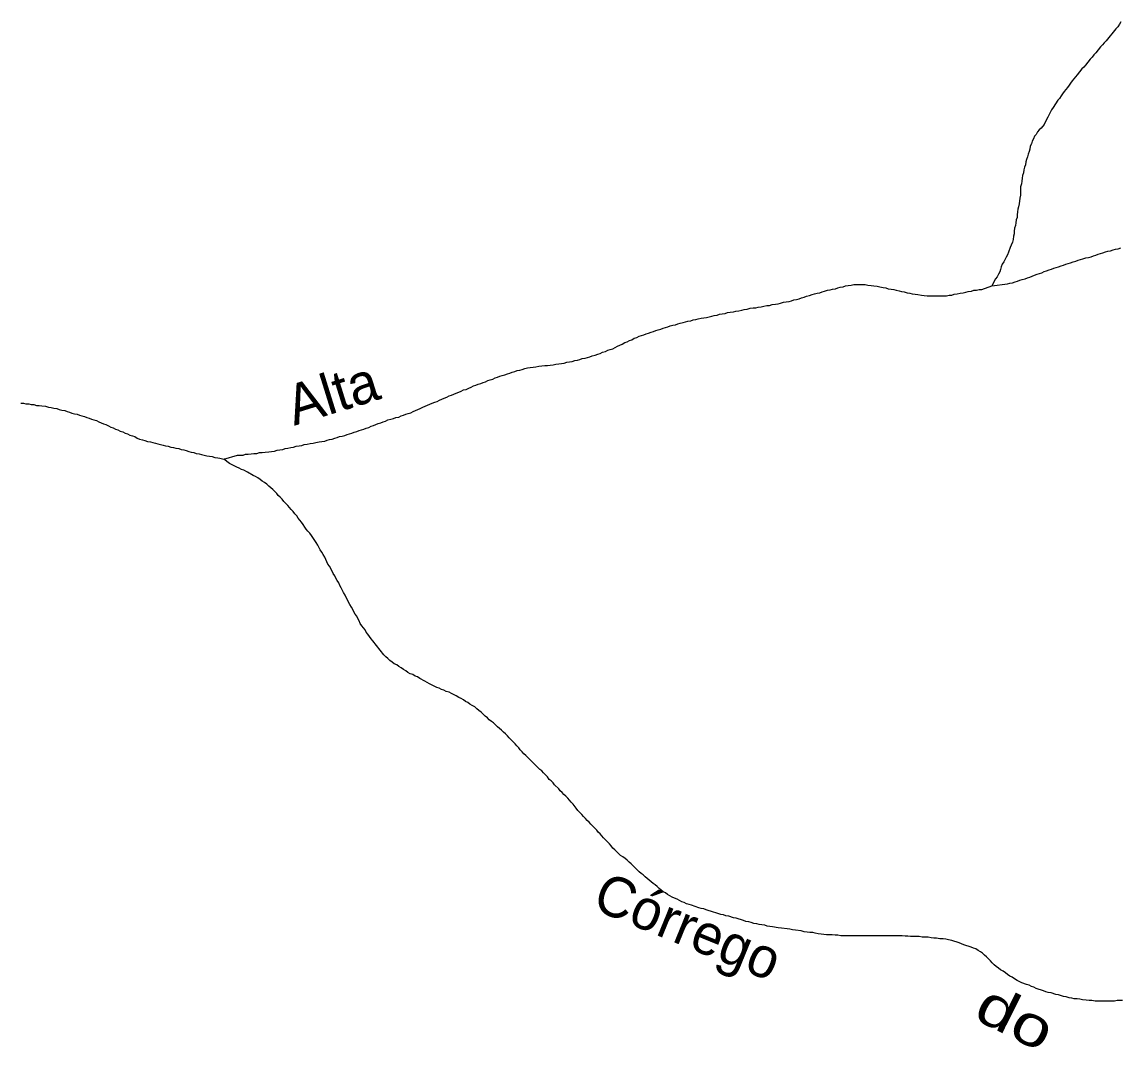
# Model space of a CAD drawing. Extents: x 652.3 to 678, y 7316.9 to 7344.9.
# Drawn here: x 668.434 to 670.618, y 7334.156 to 7336.197 of the extents above; entities that cross this region are included whole.
import ezdxf
from ezdxf.enums import TextEntityAlignment as Align

# ---------------------------------------------------------------- set-up
doc = ezdxf.new("R2010")
doc.units = 0
doc.header["$LTSCALE"] = 0.032
doc.layers.add('61', color=7, linetype='Continuous')
doc.layers.add('7', color=7, linetype='Continuous', lineweight=25)

msp = doc.modelspace()

# ---------------------------------------------------------------- linework, layer by layer
at = {"layer": '7'}
msp.add_line((668.8274, 7335.3292), (668.8353, 7335.3276), dxfattribs=at)
for points in [[(670.62, 7336.1973), (670.6169, 7336.1926), (670.6137, 7336.1878), (670.6097, 7336.1838), (670.5906, 7336.1599), (670.5866, 7336.1559), (670.5834, 7336.152), (670.5795, 7336.148), (670.5699, 7336.1361), (670.5659, 7336.1321), (670.5627, 7336.1273), (670.5588, 7336.1233), (670.5492, 7336.1114), (670.546, 7336.1074), (670.5421, 7336.1042), (670.5325, 7336.0923), (670.5293, 7336.0883), (670.523, 7336.0804), (670.5198, 7336.0756), (670.5166, 7336.0716), (670.5134, 7336.0668), (670.5102, 7336.0629), (670.507, 7336.0589), (670.5039, 7336.0541), (670.5007, 7336.0501), (670.4975, 7336.0453), (670.4943, 7336.0414), (670.4848, 7336.027), (670.4816, 7336.0223), (670.4744, 7336.008), (670.472, 7336.0032), (670.4673, 7335.9936), (670.4609, 7335.9857), (670.4569, 7335.9825), (670.4537, 7335.9785), (670.4514, 7335.9737), (670.4482, 7335.9698), (670.4458, 7335.965), (670.4434, 7335.9602), (670.4418, 7335.9546), (670.4394, 7335.9499), (670.4386, 7335.9443), (670.437, 7335.9395), (670.4354, 7335.934), (670.4338, 7335.9292), (670.4323, 7335.9236), (670.4307, 7335.9188), (670.4299, 7335.9133), (670.4283, 7335.9085), (670.4267, 7335.9029), (670.4259, 7335.8974), (670.4243, 7335.8918), (670.4235, 7335.8862), (670.4227, 7335.8806), (670.4219, 7335.8751), (670.4203, 7335.8695), (670.4203, 7335.8528), (670.4187, 7335.8464), (670.4171, 7335.8353), (670.4163, 7335.8297), (670.4147, 7335.8249), (670.414, 7335.8194), (670.4132, 7335.8138), (670.4132, 7335.8082), (670.4116, 7335.8035), (670.4108, 7335.7979), (670.41, 7335.7923), (670.4084, 7335.7868), (670.4076, 7335.7812), (670.4076, 7335.7756), (670.406, 7335.7708), (670.4052, 7335.7645), (670.4044, 7335.7589), (670.4012, 7335.7533), (670.3996, 7335.7486), (670.3964, 7335.739), (670.3941, 7335.7342), (670.3917, 7335.7295), (670.3869, 7335.7199), (670.3837, 7335.7151), (670.3813, 7335.7104), (670.3805, 7335.7048), (670.3789, 7335.7), (670.3766, 7335.6952), (670.3734, 7335.6905), (670.3702, 7335.6865), (670.363, 7335.6722)], [(670.363, 7335.6722), (670.3941, 7335.6761), (670.3988, 7335.6777), (670.4044, 7335.6785), (670.4092, 7335.6801), (670.414, 7335.6817), (670.4187, 7335.6833), (670.4235, 7335.6849), (670.4291, 7335.6865), (670.4338, 7335.6881), (670.4386, 7335.6897), (670.4434, 7335.6913), (670.4482, 7335.6937), (670.4529, 7335.6952), (670.4577, 7335.6968), (670.4625, 7335.6984), (670.4673, 7335.7008), (670.472, 7335.7024), (670.4768, 7335.704), (670.4816, 7335.7056), (670.4864, 7335.7072), (670.4911, 7335.7088), (670.4959, 7335.7104), (670.5007, 7335.712), (670.5055, 7335.7135), (670.5102, 7335.7151), (670.515, 7335.7167), (670.5198, 7335.7183), (670.5246, 7335.7199), (670.5301, 7335.7215), (670.5349, 7335.7231), (670.5397, 7335.7247), (670.5444, 7335.7263), (670.55, 7335.7279), (670.5556, 7335.7287), (670.5604, 7335.7303), (670.5651, 7335.7318), (670.5699, 7335.7334), (670.5747, 7335.735), (670.5795, 7335.7366), (670.5842, 7335.7382), (670.589, 7335.7398), (670.5938, 7335.7414), (670.5993, 7335.7422), (670.6041, 7335.7438), (670.6089, 7335.7454), (670.6145, 7335.7462), (670.62, 7335.7478)], [(669.6374, 7335.5608), (669.6421, 7335.5632), (669.6469, 7335.5648), (669.6517, 7335.5679), (669.6565, 7335.5695), (669.6612, 7335.5719), (669.666, 7335.5735), (669.6708, 7335.5751), (669.6756, 7335.5767), (669.6803, 7335.5783), (669.6851, 7335.5799), (669.6899, 7335.5815), (669.6947, 7335.5831), (669.6994, 7335.5846), (669.7042, 7335.5862), (669.709, 7335.5878), (669.7137, 7335.5894), (669.7185, 7335.591), (669.7233, 7335.5926), (669.7281, 7335.5942), (669.7336, 7335.595), (669.7384, 7335.5966), (669.7432, 7335.5982), (669.7488, 7335.599), (669.7535, 7335.6006), (669.7583, 7335.6022), (669.7639, 7335.6029), (669.7687, 7335.6045), (669.7742, 7335.6053), (669.779, 7335.6069), (669.7846, 7335.6077), (669.7901, 7335.6085), (669.7957, 7335.6093), (669.8005, 7335.6109), (669.806, 7335.6117), (669.8108, 7335.6133), (669.8164, 7335.6141), (669.8212, 7335.6157), (669.8267, 7335.6165), (669.8323, 7335.6173), (669.8371, 7335.6189), (669.8426, 7335.6197), (669.849, 7335.6205), (669.8538, 7335.622), (669.8594, 7335.6228), (669.8657, 7335.6236), (669.8705, 7335.6252), (669.8761, 7335.626), (669.8824, 7335.6276), (669.888, 7335.6284), (669.8936, 7335.6284), (669.8983, 7335.63), (669.9039, 7335.6308), (669.9095, 7335.6316), (669.9151, 7335.6332), (669.9206, 7335.6332), (669.9262, 7335.6348), (669.9326, 7335.6356), (669.9381, 7335.6364), (669.9429, 7335.638), (669.9485, 7335.6395), (669.954, 7335.6403), (669.9596, 7335.6411), (669.9644, 7335.6427), (669.9692, 7335.6443), (669.9747, 7335.6451), (669.9795, 7335.6467), (669.9843, 7335.6483), (669.9899, 7335.6499), (669.9946, 7335.6515), (670.0002, 7335.6531), (670.0058, 7335.6547), (670.0105, 7335.6563), (670.0153, 7335.6578), (670.0209, 7335.6586), (670.0257, 7335.6602), (670.0304, 7335.6618), (670.036, 7335.6634), (670.0416, 7335.6642), (670.0463, 7335.6658), (670.0519, 7335.6666), (670.0567, 7335.6682), (670.0615, 7335.6698), (670.067, 7335.6706), (670.0718, 7335.6722), (670.0774, 7335.673), (670.0829, 7335.6738), (670.0885, 7335.6746), (670.0941, 7335.6746), (670.0997, 7335.6746), (670.1052, 7335.6746), (670.1108, 7335.6746), (670.1164, 7335.6738), (670.1227, 7335.673), (670.1283, 7335.6722), (670.1347, 7335.6714), (670.1402, 7335.6706), (670.1466, 7335.669), (670.1522, 7335.6682), (670.1569, 7335.6666), (670.1625, 7335.6658)], [(670.1625, 7335.6658), (670.1681, 7335.665), (670.1729, 7335.6634), (670.1784, 7335.6626), (670.1832, 7335.661), (670.1888, 7335.6602), (670.1943, 7335.6586), (670.1999, 7335.6578), (670.2047, 7335.6563), (670.2103, 7335.6555), (670.2158, 7335.6547), (670.223, 7335.6539), (670.2286, 7335.6531), (670.2341, 7335.6523), (670.2397, 7335.6523), (670.2453, 7335.6523), (670.2508, 7335.6523), (670.2564, 7335.6523), (670.262, 7335.6523), (670.2675, 7335.6523), (670.2731, 7335.6523), (670.2779, 7335.6539), (670.2835, 7335.6539), (670.2882, 7335.6555), (670.2938, 7335.6563), (670.3002, 7335.6578), (670.3057, 7335.6586), (670.3113, 7335.6594), (670.3161, 7335.661), (670.3224, 7335.6618), (670.3272, 7335.6634), (670.3328, 7335.6634), (670.3376, 7335.665), (670.3429, 7335.665)], [(670.3429, 7335.665), (670.363, 7335.6722), (670.363, 7335.6722)], [(669.1377, 7335.3961), (669.1424, 7335.3985), (669.1472, 7335.4), (669.152, 7335.4016), (669.1568, 7335.4032), (669.1615, 7335.4056), (669.1671, 7335.4072), (669.1727, 7335.408), (669.1775, 7335.4104), (669.183, 7335.4112), (669.1878, 7335.4136), (669.1926, 7335.4152), (669.1973, 7335.4168), (669.2021, 7335.4183), (669.2069, 7335.4199), (669.2117, 7335.4223), (669.2164, 7335.4239), (669.2212, 7335.4263), (669.226, 7335.4279), (669.2308, 7335.4311), (669.2355, 7335.4327), (669.2403, 7335.4351), (669.2451, 7335.4366), (669.2499, 7335.439), (669.2546, 7335.4406), (669.2594, 7335.4422), (669.2642, 7335.4446), (669.269, 7335.447), (669.2737, 7335.4486), (669.2785, 7335.451), (669.2833, 7335.4534), (669.2881, 7335.4549), (669.2928, 7335.4565), (669.2976, 7335.4589), (669.3024, 7335.4605), (669.3072, 7335.4629), (669.3119, 7335.4653), (669.3175, 7335.4661), (669.3223, 7335.4685), (669.327, 7335.4709), (669.3318, 7335.4732), (669.3366, 7335.4748), (669.3414, 7335.4764), (669.3461, 7335.478), (669.3509, 7335.4796), (669.3557, 7335.4812), (669.3605, 7335.4836), (669.3652, 7335.4852), (669.37, 7335.4868), (669.3748, 7335.4892), (669.3796, 7335.4908), (669.3843, 7335.4923), (669.3891, 7335.4939), (669.3939, 7335.4955), (669.3995, 7335.4971), (669.4042, 7335.4987), (669.409, 7335.5003), (669.4138, 7335.5019), (669.4185, 7335.5035), (669.4241, 7335.5043), (669.4289, 7335.5059), (669.4337, 7335.5075), (669.4392, 7335.5091), (669.4448, 7335.5099), (669.4504, 7335.5106), (669.4559, 7335.5114), (669.4615, 7335.5122), (669.4679, 7335.513), (669.4735, 7335.5138), (669.479, 7335.5138), (669.4846, 7335.5146), (669.4902, 7335.5154), (669.4957, 7335.5162), (669.5013, 7335.517), (669.5069, 7335.5178), (669.5124, 7335.5186), (669.5172, 7335.5202), (669.5228, 7335.521), (669.5284, 7335.5218), (669.5331, 7335.5234), (669.5387, 7335.5242), (669.5435, 7335.5258), (669.5482, 7335.5274), (669.5538, 7335.5282), (669.5586, 7335.5297), (669.5634, 7335.5313), (669.5681, 7335.5329), (669.5737, 7335.5345), (669.5793, 7335.5361), (669.5841, 7335.5377), (669.5888, 7335.5401), (669.5944, 7335.5417), (669.5992, 7335.5441), (669.6039, 7335.5457), (669.6087, 7335.5472), (669.6135, 7335.5496), (669.6183, 7335.552), (669.623, 7335.5544), (669.6278, 7335.556), (669.6326, 7335.5592), (669.6374, 7335.5608)], [(668.4311, 7335.439), (668.4367, 7335.439), (668.4414, 7335.4374), (668.447, 7335.4374), (668.4518, 7335.4359), (668.4574, 7335.4359), (668.4621, 7335.4343), (668.4677, 7335.4343), (668.4733, 7335.4335), (668.4804, 7335.4327), (668.486, 7335.4311), (668.4916, 7335.4303), (668.4971, 7335.4287), (668.5027, 7335.4279), (668.5075, 7335.4263), (668.5131, 7335.4247), (668.5186, 7335.4239), (668.5234, 7335.4223), (668.5282, 7335.4207), (668.5329, 7335.4191), (668.5377, 7335.4176), (668.5433, 7335.4168), (668.5481, 7335.4152), (668.5528, 7335.4136), (668.5576, 7335.412), (668.5624, 7335.4104), (668.5672, 7335.4088), (668.5719, 7335.4072), (668.5767, 7335.4056), (668.5815, 7335.404), (668.5863, 7335.4016), (668.591, 7335.4)], [(668.591, 7335.4), (668.5958, 7335.3977), (668.6006, 7335.3961), (668.6054, 7335.3937), (668.6101, 7335.3913), (668.6149, 7335.3897), (668.6197, 7335.3873), (668.6245, 7335.3857), (668.6292, 7335.3833), (668.634, 7335.3817), (668.6388, 7335.3794), (668.6435, 7335.3778), (668.6483, 7335.3754), (668.6531, 7335.3738), (668.6579, 7335.3722), (668.6626, 7335.369), (668.6674, 7335.3674), (668.673, 7335.3658), (668.6778, 7335.3642), (668.6833, 7335.3626), (668.6889, 7335.3619), (668.6937, 7335.3603), (668.6992, 7335.3595), (668.704, 7335.3579), (668.7088, 7335.3563), (668.7144, 7335.3555), (668.7191, 7335.3539), (668.7247, 7335.3531), (668.7295, 7335.3515), (668.7351, 7335.3507), (668.7398, 7335.3491), (668.7454, 7335.3483), (668.7502, 7335.3467), (668.7557, 7335.3459), (668.7605, 7335.3443), (668.7653, 7335.3428), (668.7701, 7335.3412), (668.7756, 7335.3404), (668.7804, 7335.3388), (668.786, 7335.338), (668.7907, 7335.3364), (668.7963, 7335.3356), (668.8011, 7335.334), (668.8067, 7335.3332), (668.8122, 7335.3324), (668.817, 7335.3308), (668.8234, 7335.33), (668.8274, 7335.3292)], [(668.8353, 7335.3276), (668.8624, 7335.3356), (668.8679, 7335.3356), (668.8735, 7335.3356), (668.8783, 7335.3372), (668.8838, 7335.3372), (668.8894, 7335.338), (668.895, 7335.3388), (668.9006, 7335.3388), (668.9061, 7335.3404), (668.9117, 7335.3404), (668.9173, 7335.3412), (668.9244, 7335.342), (668.93, 7335.3428), (668.9356, 7335.3436), (668.9411, 7335.3451), (668.9467, 7335.3459), (668.9523, 7335.3467), (668.957, 7335.3483), (668.9626, 7335.3491), (668.9682, 7335.3507), (668.9738, 7335.3515), (668.9793, 7335.3531), (668.9849, 7335.3539), (668.9905, 7335.3547), (668.9952, 7335.3563), (669.0008, 7335.3571), (669.0072, 7335.3587), (669.0127, 7335.3595), (669.0183, 7335.3603), (669.0247, 7335.3619), (669.0303, 7335.3626), (669.0358, 7335.3634), (669.0406, 7335.365), (669.0454, 7335.3666), (669.0509, 7335.3674), (669.0557, 7335.369), (669.0605, 7335.3706), (669.0653, 7335.3722), (669.0708, 7335.373), (669.0756, 7335.3746), (669.0804, 7335.3762), (669.0852, 7335.3778), (669.0899, 7335.3794), (669.0947, 7335.3809), (669.0995, 7335.3825), (669.1043, 7335.3841), (669.109, 7335.3857), (669.1138, 7335.3873), (669.1186, 7335.3889), (669.1233, 7335.3905), (669.1281, 7335.3929), (669.1329, 7335.3945), (669.1377, 7335.3961)], [(668.9117, 7335.2839), (668.9077, 7335.2871), (668.9029, 7335.2902), (668.8982, 7335.2926), (668.8934, 7335.295), (668.8823, 7335.3014), (668.8751, 7335.3054), (668.8703, 7335.307), (668.8655, 7335.3093), (668.8608, 7335.3117), (668.8464, 7335.3189), (668.8353, 7335.3276)], [(669.3597, 7334.8128), (669.3549, 7334.816), (669.3469, 7334.824), (669.3422, 7334.8272), (669.3382, 7334.8303), (669.3342, 7334.8343), (669.3294, 7334.8375), (669.3247, 7334.8399), (669.3207, 7334.8431), (669.3159, 7334.8455), (669.3119, 7334.8486), (669.3072, 7334.851), (669.3024, 7334.8534), (669.2976, 7334.8566), (669.2881, 7334.8614), (669.2833, 7334.8638), (669.2777, 7334.8653), (669.2729, 7334.8677), (669.2682, 7334.8693), (669.2634, 7334.8717), (669.2586, 7334.8733), (669.2443, 7334.8805), (669.2395, 7334.8828), (669.2347, 7334.886), (669.2252, 7334.8908), (669.2204, 7334.894), (669.2156, 7334.8956), (669.2109, 7334.8988), (669.2061, 7334.9004), (669.2013, 7334.9027), (669.1973, 7334.9059), (669.1926, 7334.9091), (669.1878, 7334.9123), (669.183, 7334.9147), (669.179, 7334.9179), (669.1743, 7334.9202), (669.1703, 7334.9234), (669.1655, 7334.9266), (669.1615, 7334.9306), (669.1576, 7334.9338), (669.1536, 7334.9378), (669.1313, 7334.9656), (669.1281, 7334.9696), (669.1249, 7334.9744), (669.1218, 7334.9791), (669.1186, 7334.9831), (669.1162, 7334.9879), (669.1098, 7334.9958), (669.1066, 7335.0006), (669.1043, 7335.0054), (669.1019, 7335.0102), (669.0995, 7335.0149), (669.0963, 7335.0189), (669.0891, 7335.0332), (669.086, 7335.038), (669.0788, 7335.0523), (669.0764, 7335.0571), (669.0732, 7335.0619), (669.0684, 7335.0714), (669.0661, 7335.0762), (669.0637, 7335.081), (669.0605, 7335.0857), (669.0581, 7335.0905), (669.0557, 7335.0953), (669.0525, 7335.1001), (669.0478, 7335.1096), (669.0454, 7335.1144), (669.0422, 7335.1184), (669.0398, 7335.1231), (669.0382, 7335.1279), (669.0358, 7335.1327), (669.0326, 7335.1375), (669.0303, 7335.1422), (669.0271, 7335.147), (669.0223, 7335.1566), (669.0191, 7335.1613), (669.0096, 7335.1757), (669.0064, 7335.1804), (669.0024, 7335.1844), (668.9992, 7335.1884), (668.996, 7335.1924), (668.9929, 7335.1971), (668.9897, 7335.2019), (668.9833, 7335.2099), (668.9801, 7335.2147), (668.9761, 7335.2186), (668.973, 7335.2234), (668.969, 7335.2274), (668.9626, 7335.2353), (668.9586, 7335.2393), (668.9547, 7335.2433), (668.9515, 7335.2481), (668.9475, 7335.252), (668.9435, 7335.2552), (668.9403, 7335.2592), (668.9324, 7335.2672), (668.9284, 7335.2703), (668.9244, 7335.2735), (668.9204, 7335.2775), (668.9157, 7335.2807), (668.9117, 7335.2839)], [(669.8952, 7334.403), (669.8896, 7334.4038), (669.884, 7334.4054), (669.8793, 7334.407), (669.8737, 7334.4078), (669.8689, 7334.4094), (669.8546, 7334.4142), (669.849, 7334.415), (669.8395, 7334.4182), (669.8339, 7334.419), (669.8291, 7334.4206), (669.8236, 7334.4213), (669.814, 7334.4245), (669.8092, 7334.4261), (669.7949, 7334.4309), (669.7901, 7334.4325), (669.7846, 7334.4333), (669.7798, 7334.4349), (669.7655, 7334.4397), (669.7607, 7334.4412), (669.7559, 7334.4428), (669.7511, 7334.4452), (669.7464, 7334.4468), (669.7368, 7334.4516), (669.732, 7334.454), (669.7273, 7334.4556), (669.7225, 7334.4587), (669.7177, 7334.4611), (669.7137, 7334.4643), (669.709, 7334.4667), (669.705, 7334.4699), (669.701, 7334.4731), (669.697, 7334.477), (669.6931, 7334.4802), (669.6891, 7334.4834), (669.6851, 7334.4866), (669.6811, 7334.4898), (669.6771, 7334.493), (669.6732, 7334.4961), (669.6692, 7334.5001), (669.6652, 7334.5033), (669.6612, 7334.5065), (669.6453, 7334.5224), (669.6413, 7334.5256), (669.6374, 7334.5296), (669.6334, 7334.5327), (669.6286, 7334.5359), (669.6246, 7334.5391), (669.6207, 7334.5423), (669.6127, 7334.5503), (669.6087, 7334.5534), (669.6055, 7334.5582), (669.6024, 7334.5622), (669.5904, 7334.5741), (669.5841, 7334.5821), (669.5801, 7334.5853), (669.5769, 7334.5892), (669.565, 7334.6012), (669.5618, 7334.6052), (669.5578, 7334.6083), (669.5546, 7334.6123), (669.5506, 7334.6163), (669.5474, 7334.6203), (669.5395, 7334.6282), (669.5363, 7334.633), (669.5299, 7334.641), (669.526, 7334.6449), (669.5196, 7334.6529), (669.5156, 7334.6569), (669.5116, 7334.6601), (669.5085, 7334.664), (669.5045, 7334.6672), (669.5013, 7334.6712), (669.4933, 7334.6792), (669.4902, 7334.6831), (669.4862, 7334.6871), (669.4822, 7334.6903), (669.479, 7334.6951), (669.4711, 7334.703), (669.4679, 7334.707), (669.4639, 7334.7102), (669.444, 7334.7301), (669.44, 7334.7341), (669.4361, 7334.738), (669.4321, 7334.7412), (669.4289, 7334.7452), (669.4249, 7334.7492), (669.4217, 7334.7532), (669.4178, 7334.7571), (669.4146, 7334.7611), (669.4026, 7334.773), (669.3995, 7334.777), (669.3955, 7334.781), (669.3915, 7334.7842), (669.3875, 7334.7882), (669.3835, 7334.7913), (669.3796, 7334.7945), (669.3716, 7334.8025), (669.3676, 7334.8057), (669.3628, 7334.8088), (669.3597, 7334.8128)], [(670.6232, 7334.2503), (670.6121, 7334.2503), (670.6073, 7334.2487), (670.5683, 7334.2487), (670.562, 7334.2503), (670.5564, 7334.2503), (670.5508, 7334.2511), (670.5437, 7334.2519), (670.5381, 7334.2527), (670.5325, 7334.2535), (670.5269, 7334.2535), (670.5222, 7334.2551), (670.5166, 7334.2558), (670.511, 7334.2574), (670.5055, 7334.2582), (670.4959, 7334.2614), (670.4903, 7334.2622), (670.4808, 7334.2654), (670.4752, 7334.2662), (670.4704, 7334.2678), (670.4657, 7334.2694), (670.4514, 7334.2741), (670.4466, 7334.2765), (670.4418, 7334.2781), (670.437, 7334.2805), (670.4323, 7334.2821), (670.4227, 7334.2853), (670.4132, 7334.2901), (670.4084, 7334.2932), (670.4036, 7334.2964), (670.3988, 7334.2988), (670.3941, 7334.302), (670.3901, 7334.3052), (670.3853, 7334.3084), (670.3805, 7334.3115), (670.3766, 7334.3147), (670.3718, 7334.3179), (670.3678, 7334.3211), (670.3638, 7334.3251), (670.3606, 7334.329), (670.3567, 7334.333), (670.3527, 7334.337), (670.3487, 7334.3402), (670.3447, 7334.3442), (670.3408, 7334.3474), (670.336, 7334.3497), (670.3312, 7334.3529), (670.3264, 7334.3545), (670.3217, 7334.3561), (670.3073, 7334.3609), (670.3026, 7334.3633), (670.2978, 7334.3649), (670.2835, 7334.3696), (670.2771, 7334.3712), (670.2715, 7334.372), (670.266, 7334.3728), (670.2596, 7334.3728), (670.2532, 7334.3744), (670.2477, 7334.3744), (670.2421, 7334.3752), (670.2365, 7334.376), (670.2246, 7334.376), (670.2182, 7334.3776), (670.2015, 7334.3776), (670.1959, 7334.3784), (670.1904, 7334.3784), (670.1848, 7334.3792), (670.0623, 7334.3792), (670.0567, 7334.38), (670.0511, 7334.38), (670.0456, 7334.3808), (670.0344, 7334.3808), (670.0288, 7334.3816), (670.0233, 7334.3824), (670.0177, 7334.3832), (670.0113, 7334.384), (670.0066, 7334.3855), (670.001, 7334.3855), (669.9954, 7334.3863), (669.9899, 7334.3871), (669.9835, 7334.3887), (669.9723, 7334.3903), (669.9668, 7334.3911), (669.9612, 7334.3919), (669.9556, 7334.3927), (669.9445, 7334.3943), (669.9381, 7334.3951), (669.927, 7334.3967), (669.9214, 7334.3975), (669.9159, 7334.3983), (669.9111, 7334.3999), (669.9055, 7334.4007), (669.8999, 7334.4015), (669.8952, 7334.403)]]:
    msp.add_lwpolyline(points, dxfattribs=at)

# ---------------------------------------------------------------- texts
at = {"layer": '61'}
for s, rotation, p in [('Alta', 17.317, (669.0629, 7335.421)), ('Córrego', 337.777, (669.7437, 7334.3608))]:
    msp.add_text(s, height=0.08, rotation=rotation, dxfattribs=at).set_placement(p, align=Align.CENTER)
at = {"layer": '61', "width": 1.3}
msp.add_text('do', height=0.08, rotation=333.412, dxfattribs=at).set_placement((670.3923, 7334.1811), align=Align.CENTER)

doc.saveas('drawing.dxf')
